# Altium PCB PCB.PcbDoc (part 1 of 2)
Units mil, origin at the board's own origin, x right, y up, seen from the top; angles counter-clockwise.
Board outline 3149.61 x 1968.5 mil, 4 copper layers (Top, GND, Power, Bottom), stack 59.37 mil thick; 127 components, 80 nets, 529 pads, 122 vias.
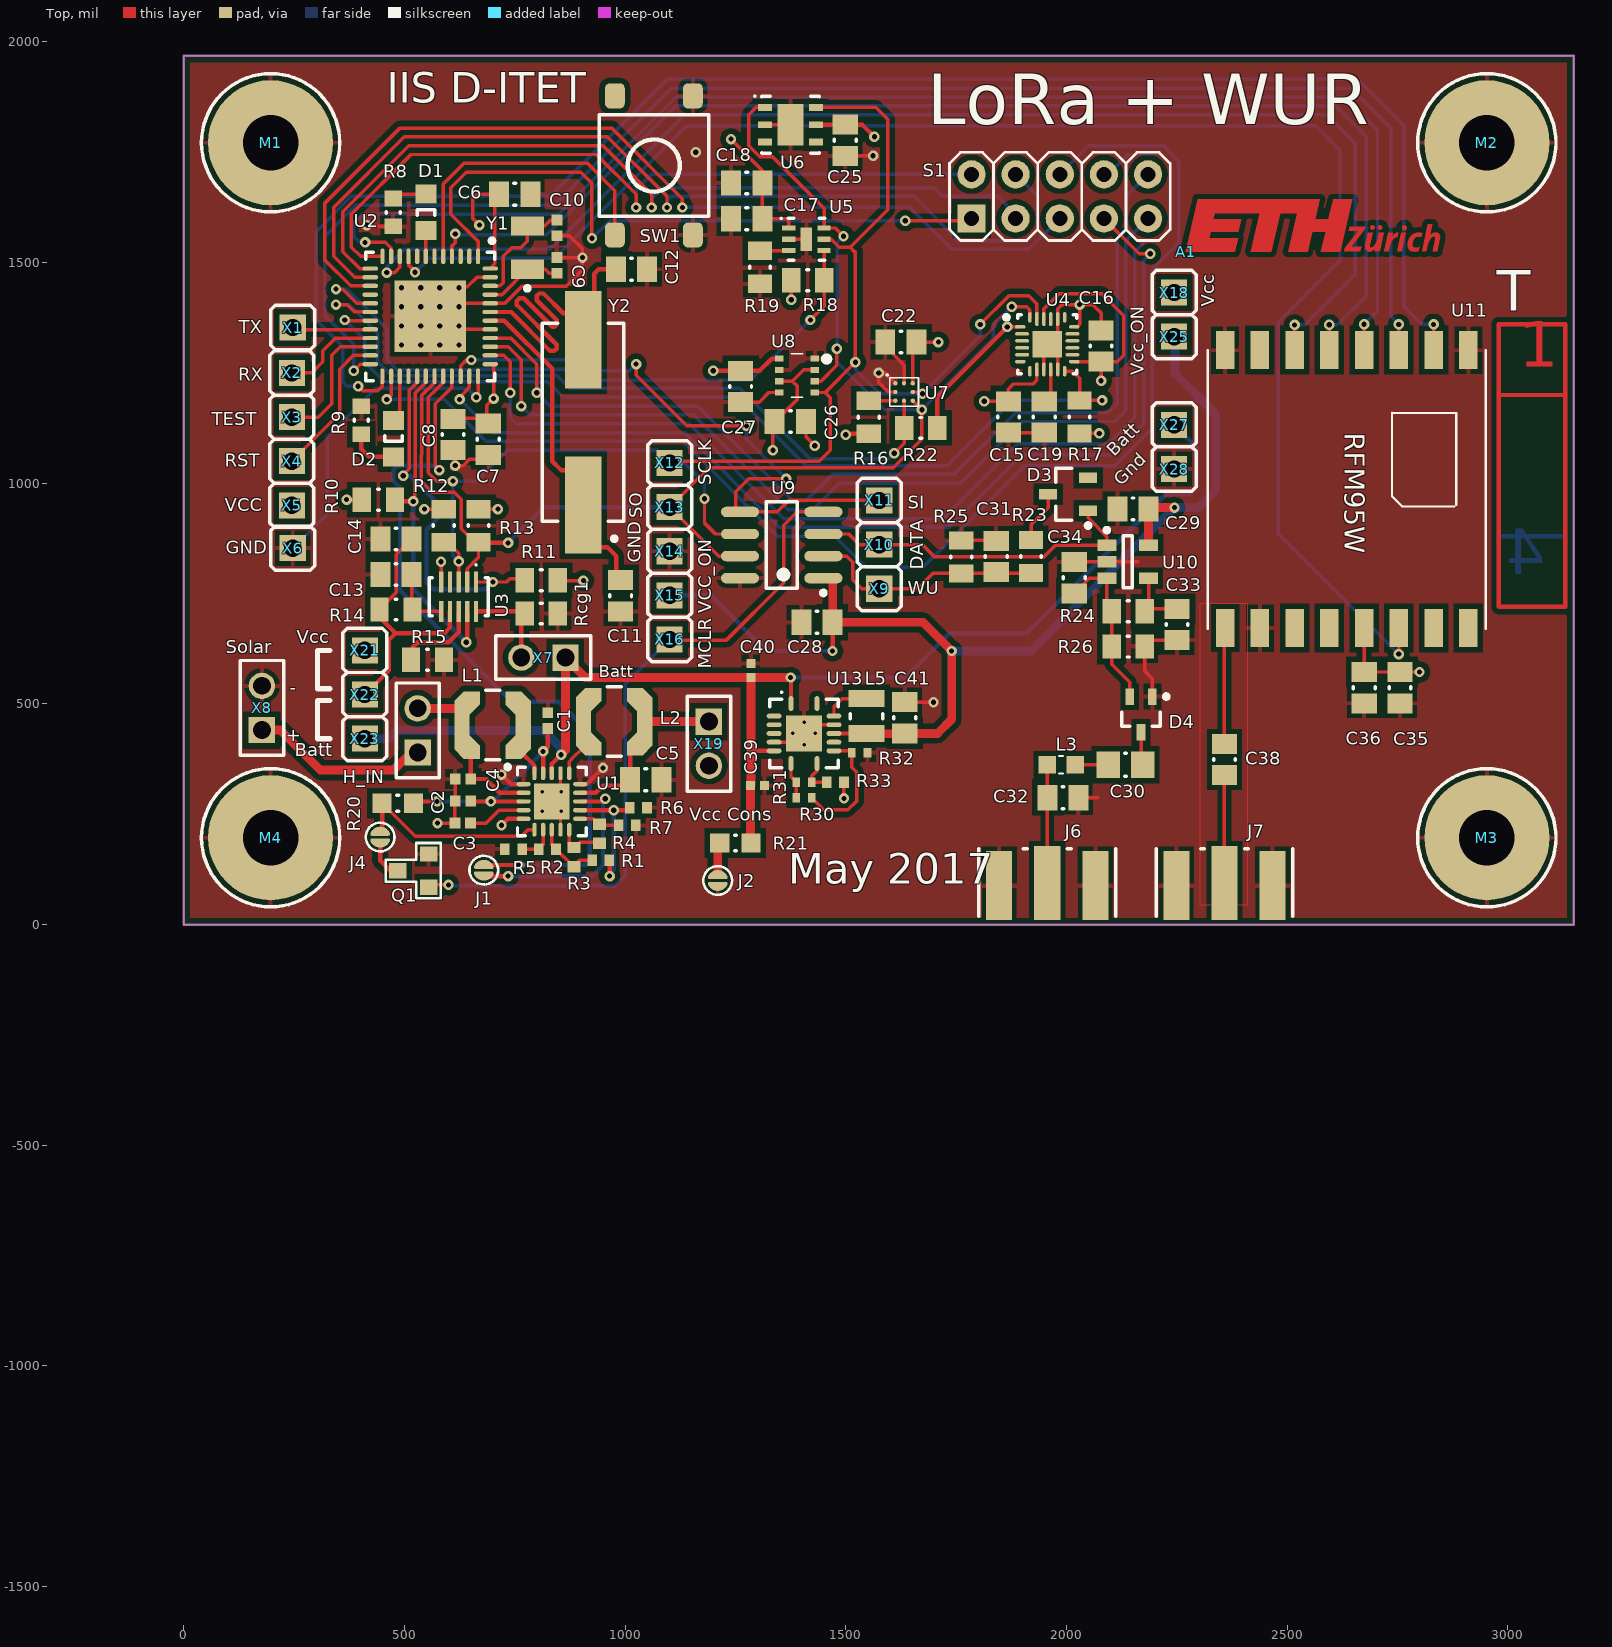
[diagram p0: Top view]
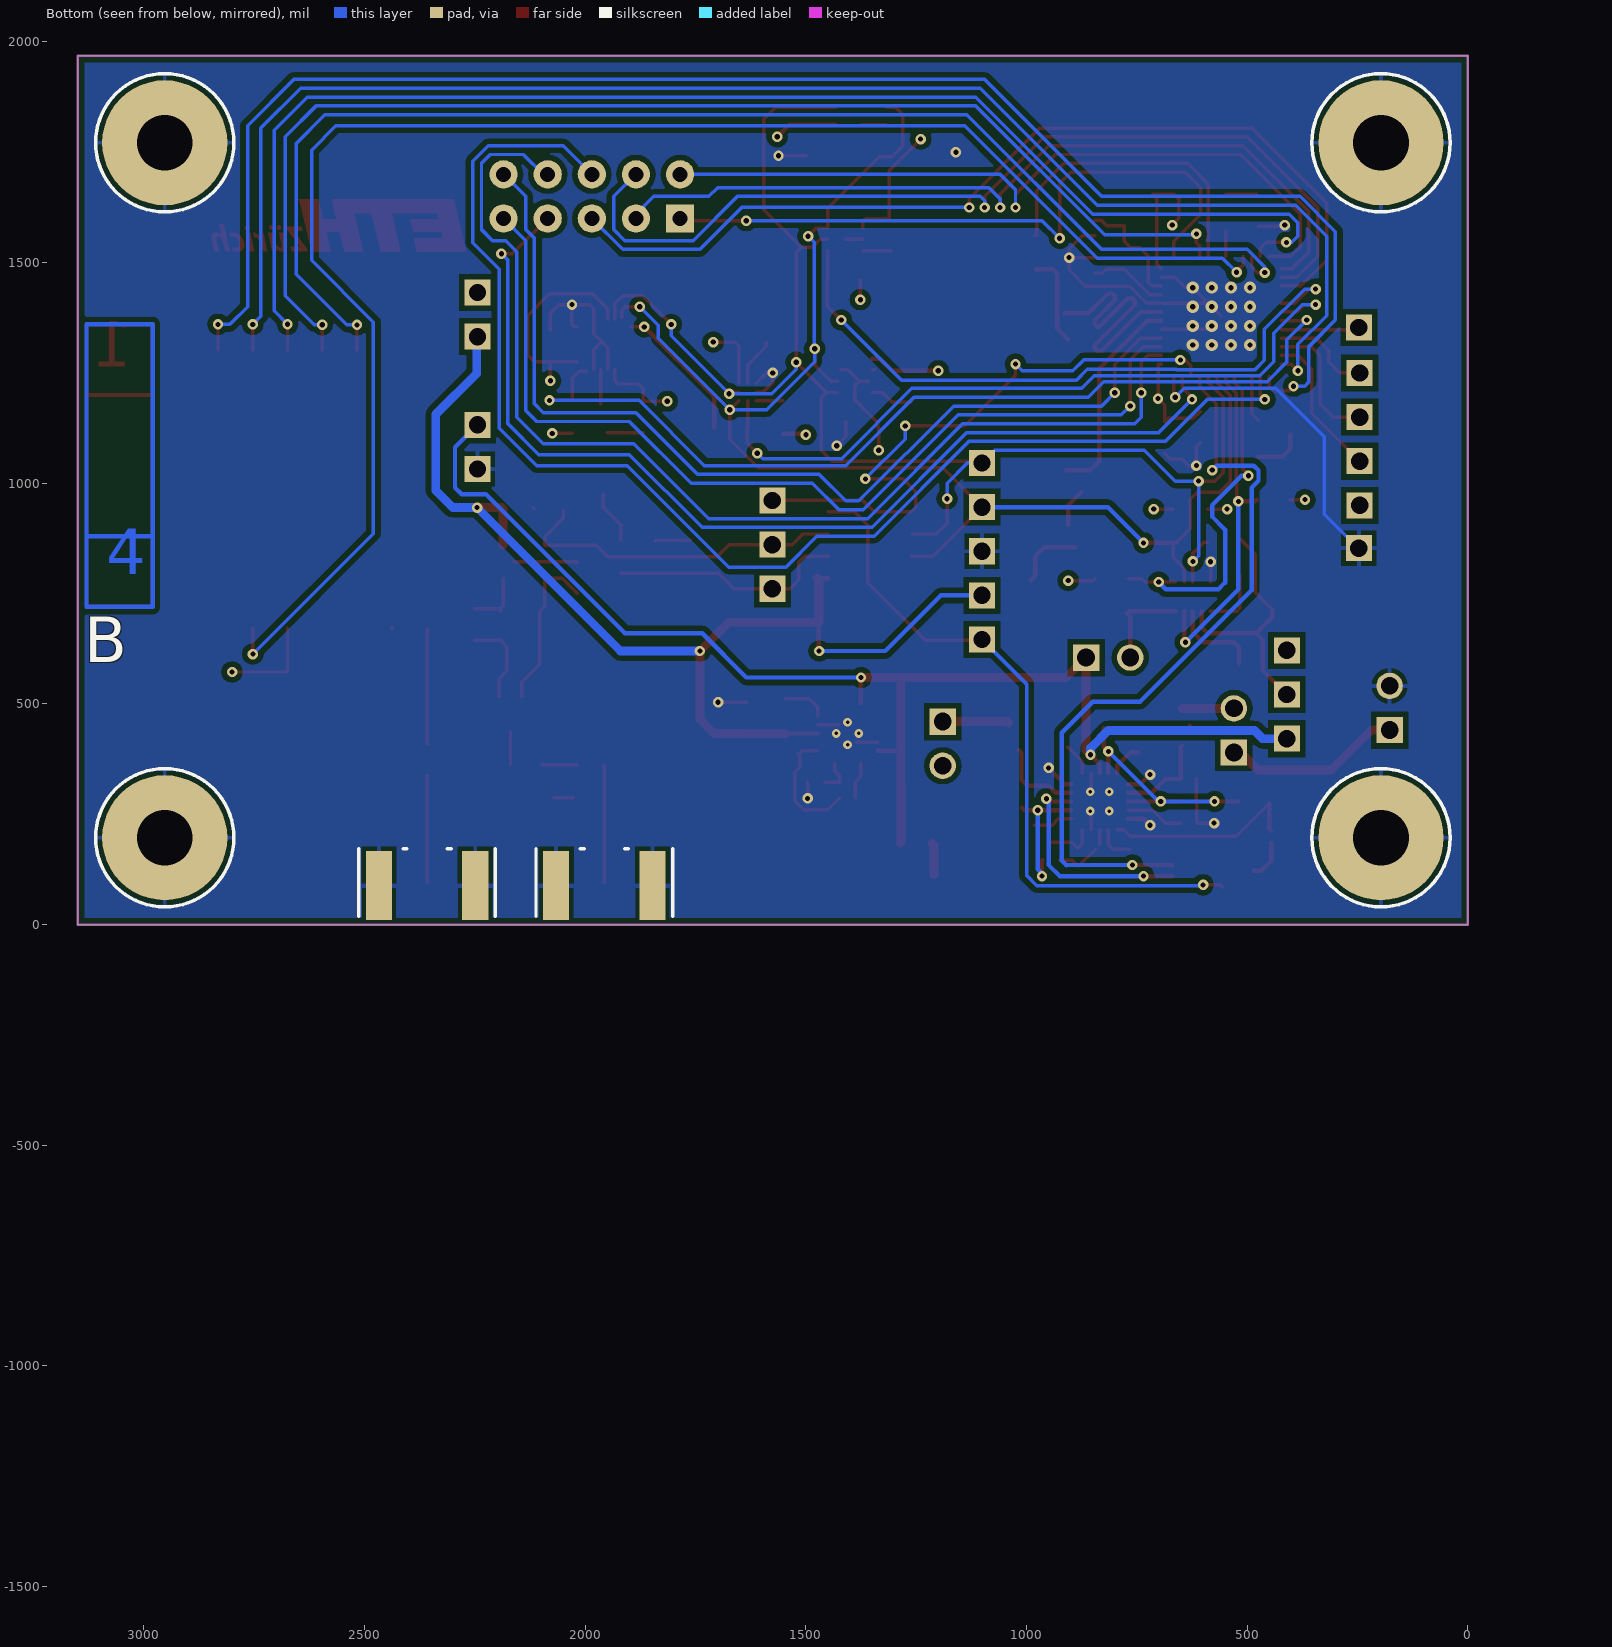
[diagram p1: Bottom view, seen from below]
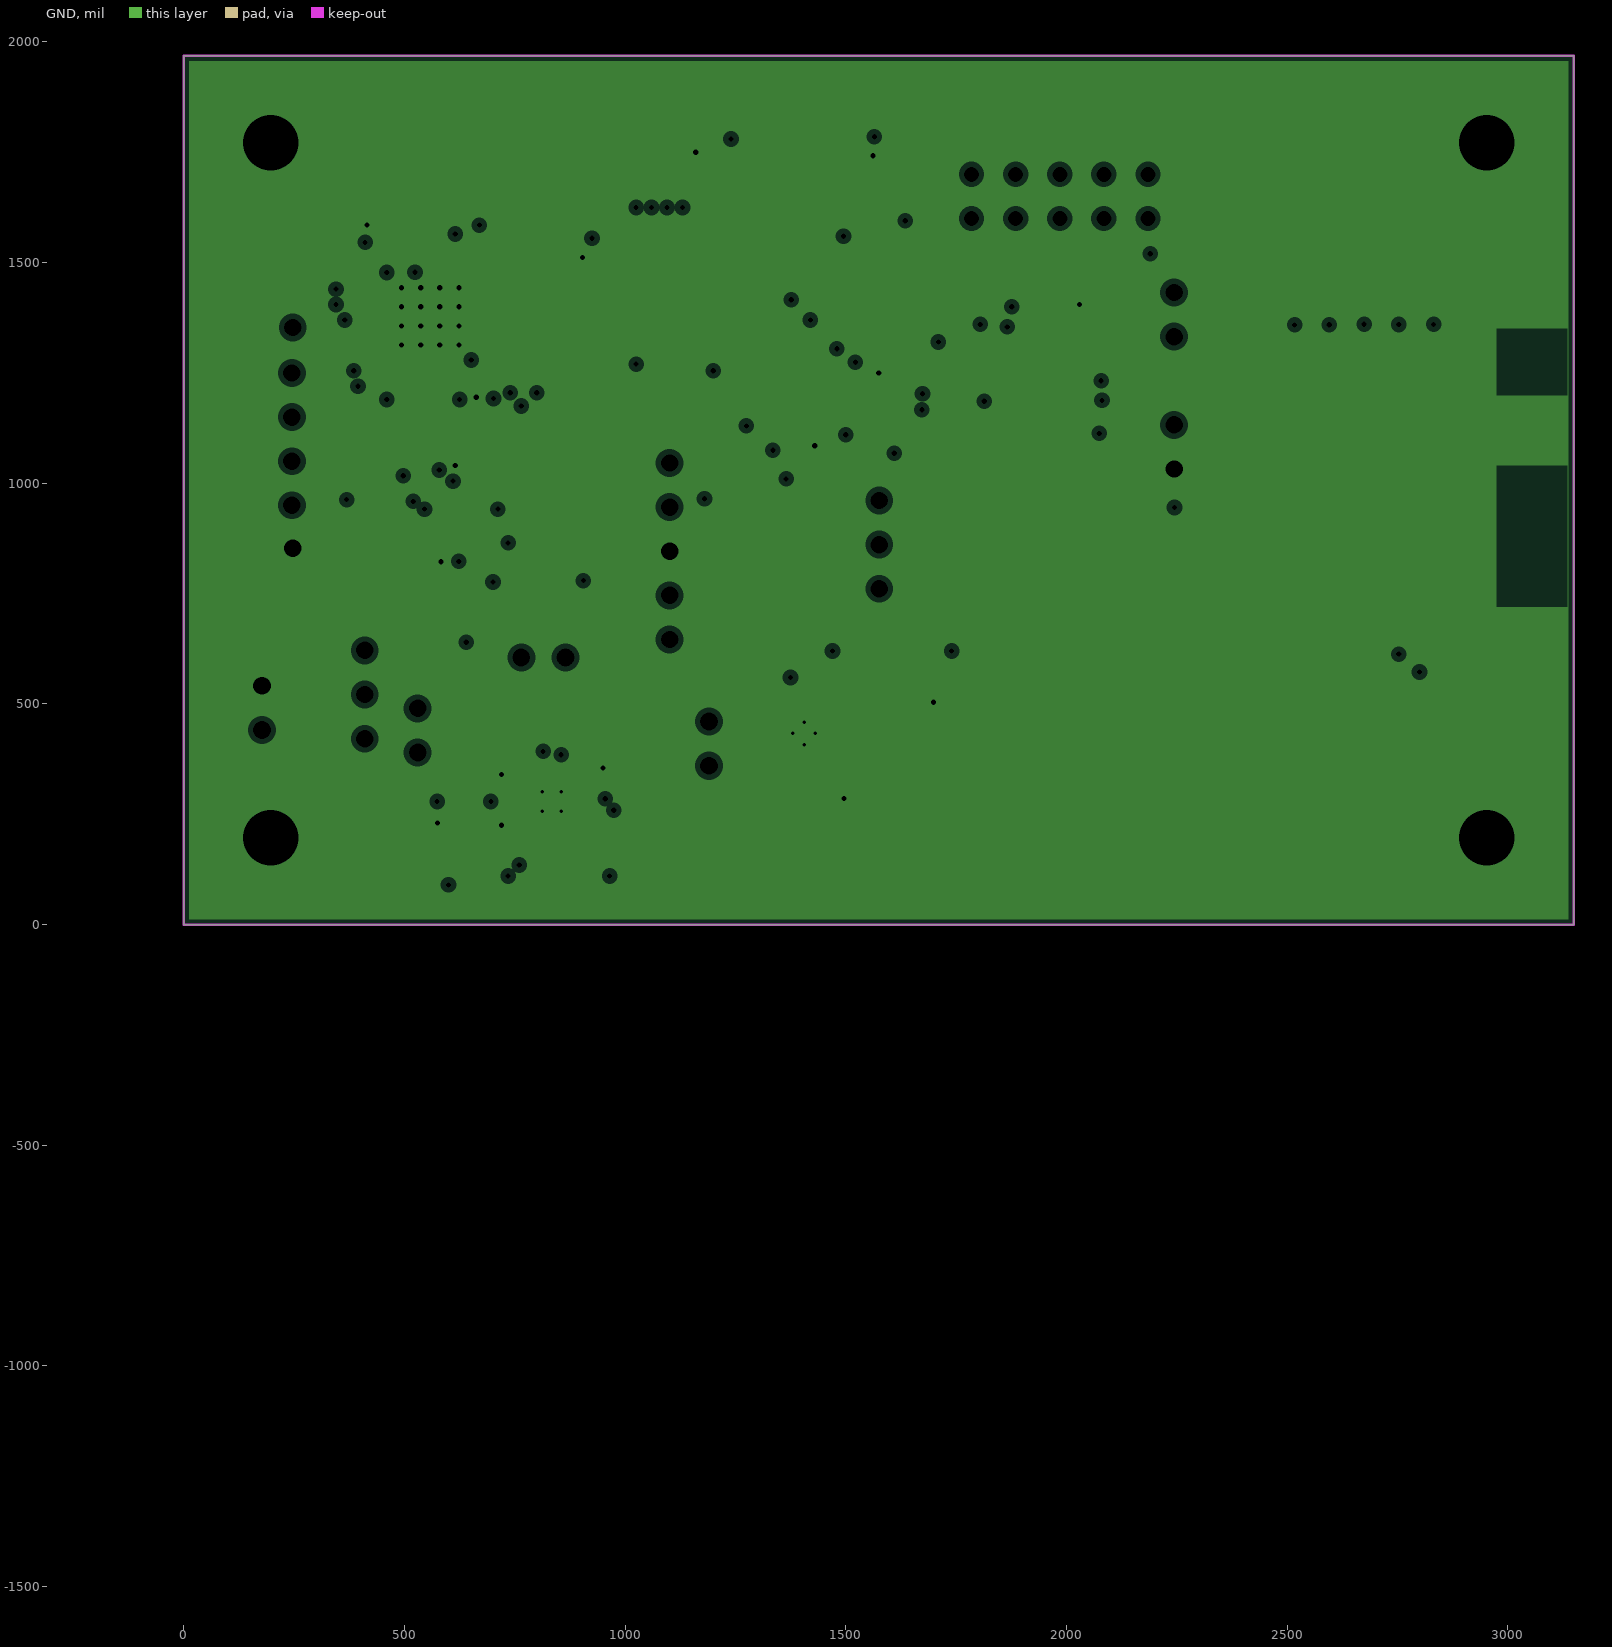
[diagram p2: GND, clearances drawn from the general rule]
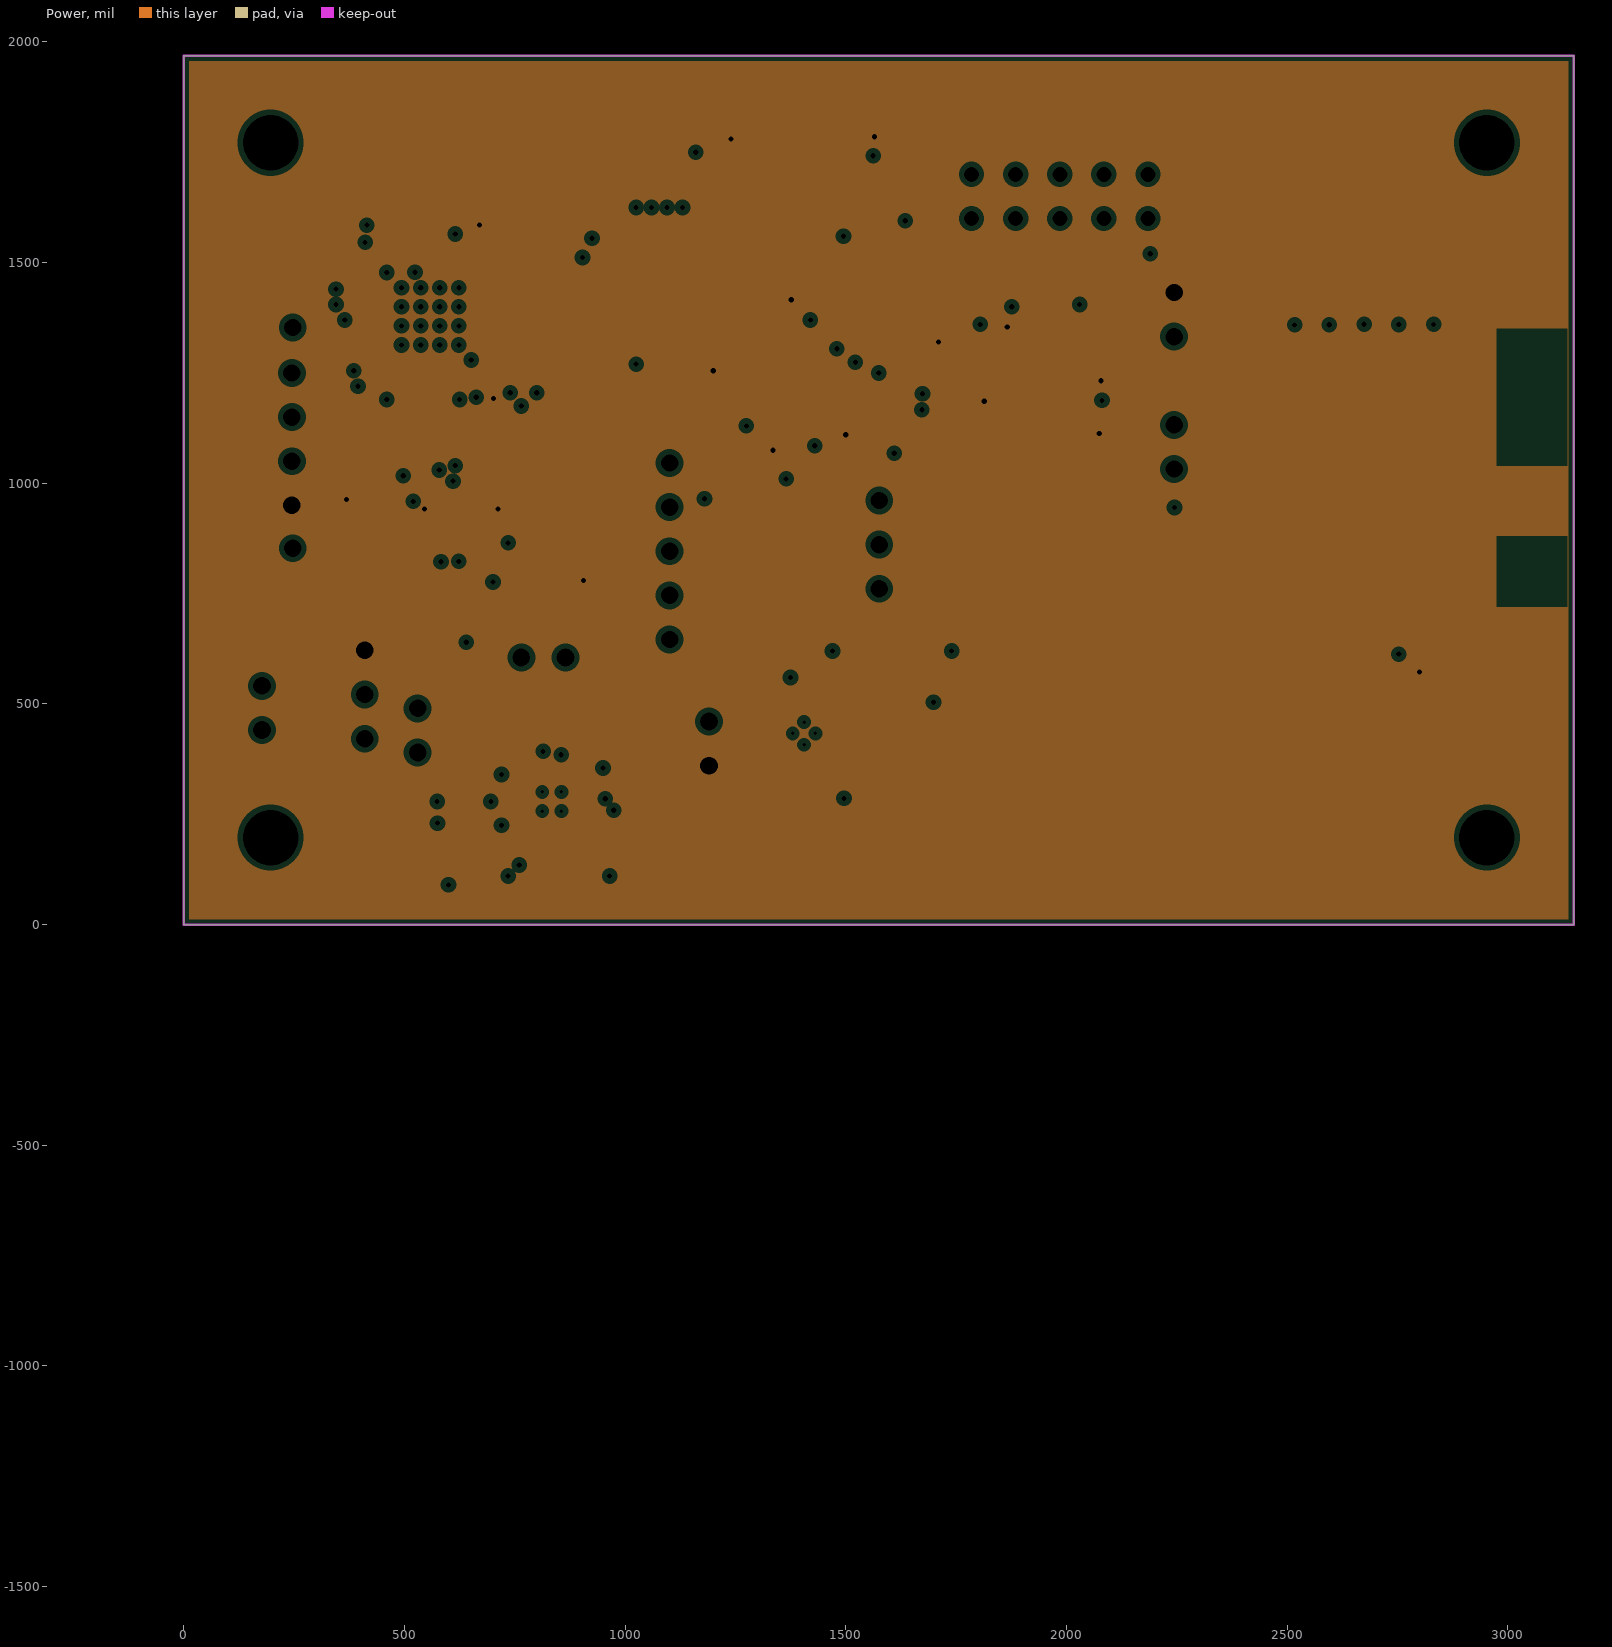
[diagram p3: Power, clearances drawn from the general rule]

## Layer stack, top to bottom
Top Solder: solder mask 0.9843, Solder Resist, Dk 3.5
Top: signal copper 1.4173
Dielectric1: prepreg 7.874, FR-4, Dk 4
GND: plane copper 0.7087, net GND
Dielectric4: core 39.3701, FR-4, Dk 4.2
Power: plane copper 0.7087, net VCC
Dielectric9: prepreg 7.874, FR-4, Dk 4.2
Bottom: signal copper 1.4173
Bottom Solder: solder mask 0.9843, Solder Resist, Dk 3.5

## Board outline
0,0 0,1968.5 3149.61,1968.5 3149.61,0

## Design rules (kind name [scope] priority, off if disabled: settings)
Clearance Clearance_Poly [InPolygon] p1: gap=12 ignorepadtopadclearanceinfootprint=FALSE except(0: Arc-Hole Track-Hole SMDPad-Hole THPad-Hole Via-Hole Fill-Hole Poly-Hole Region-Hole Text-Hole)
Clearance Clearance_RF [InNetClass('RF') vs InPolygon] p2: gap=11.81 ignorepadtopadclearanceinfootprint=FALSE except(0: Arc-Hole Track-Hole SMDPad-Hole THPad-Hole Via-Hole Fill-Hole Poly-Hole Region-Hole Text-Hole)
Clearance Clearance_SJ2 [InNet('NetJ2_1')] p3: gap=5 ignorepadtopadclearanceinfootprint=FALSE except(0: Arc-Hole Track-Hole SMDPad-Hole THPad-Hole Via-Hole Fill-Hole Poly-Hole Region-Hole Text-Hole)
Clearance Clearance_SJ4 [InNet('NetJ4_1')] p4: gap=5 ignorepadtopadclearanceinfootprint=FALSE except(0: Arc-Hole Track-Hole SMDPad-Hole THPad-Hole Via-Hole Fill-Hole Poly-Hole Region-Hole Text-Hole)
Clearance Clearance_SJ1 [InNet('NetJ1_1')] p5: gap=5 ignorepadtopadclearanceinfootprint=FALSE except(0: Arc-Hole Track-Hole SMDPad-Hole THPad-Hole Via-Hole Fill-Hole Poly-Hole Region-Hole Text-Hole)
Clearance [All] p6: gap=6 ignorepadtopadclearanceinfootprint=FALSE except(0: Arc-Hole Track-Hole SMDPad-Hole THPad-Hole Via-Hole Fill-Hole Poly-Hole Region-Hole Text-Hole)
ComponentClearance [All] p1 off: gap=10 collisioncheckmode=3 verticalgap=10 showdistances=FALSE
FabricationTestPointUsage TestPointUsage [All] p1: valid=0 allowmultiple=FALSE
FabricationTestpoint Testpoint [(IsPad And (OnTopLayer Or OnBottomLayer))] p1: side=3 testpointundercomponent=TRUE minsize=40 maxsize=100 preferedsize=60 minholesize=0 maxholesize=40 preferedholesize=32.01 testpointgrid=0.98 allowsidetop=TRUE allowsidebottom=TRUE usegrid=TRUE gridtolerance=0.01
Height [All] p1 off: minheight=0 maxheight=1000 prefheight=500
HoleSize [All] p1: absolutevalues=TRUE maxlimit=275.59 minlimit=7.87 maxpercent=80.000 minpercent=20.000
Length [InNetClass('Tektronic')] p1: maxlimit=3006 minlimit=2994
MinimumAnnularRing [All] p1 off: minimumring=5.91
MinimumSolderMaskSliver [All] p1: minsoldermaskwidth=3.9
PlaneClearance Spacer_Clearance [(InPadClass('Spacer') )] p1: clearance=78.74
PlaneClearance "Mounting holes" [(InPadClass('ExtendedClearance') )] p2: clearance=82.68
PlaneClearance [All] p3: clearance=11.81
PlaneConnect ViaInPlane [IsVia] p1: planeconnectstyle=Direct reliefexpansion=20 reliefentries=4 reliefconductorwidth=10 reliefairgap=10
PlaneConnect [All] p2: planeconnectstyle=Relief reliefexpansion=10 reliefentries=4 reliefconductorwidth=8 reliefairgap=8
PolygonConnect ViaInPolygon [IsVia] p1: connectstyle=Direct reliefconductorwidth=10 reliefentries=4 polygonreliefangle="90 Angle" airgapwidth=10
PolygonConnect [All] p2: connectstyle=Relief reliefconductorwidth=10 reliefentries=4 polygonreliefangle="90 Angle" airgapwidth=10
RoutingVias [All] p1: holewidth=11.81 width=23.62 viastyle="Through Hole" minholewidth=7.87 minwidth=17.72 maxholewidth=31.5 maxwidth=47.24
ShortCircuit ViaInPAD [InNet('No Net') vs InNet('No Net')] p1: allowed=TRUE
ShortCircuit RF_GNSs [InNet('D_GND') vs InNetClass('RF_GND')] p2: allowed=FALSE
ShortCircuit [All] p3: allowed=FALSE
SilkToSilkClearance [All] p1: silktosilkclearance=3.94
SilkToSolderMaskClearance [IsPad] p1: minsilkscreentomaskgap=3.94 clearancetoexposedcopper=TRUE
SolderMaskExpansion [All] p1: expansion=2.95
Width [All] p1: maxlimit=98.43 minlimit=5.91 preferedwidth=10 minimp=50.000000 maximp=50.000000 favimp=50.000000
19 further rules are at their usual default settings.

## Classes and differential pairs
pad class ExtendedClearance: O3216-A
pad class Vias: DPS8-A9
pad class Sense: DPS1-A6 DPS1-A12 DPS1-B5 DPS1-B7 DPS1-B11 DPS1-B13 DPS1-B17 DPS1-C2 DPS1-C6 DPS1-C12 DPS1-C16 DPS2-A6 DPS2-A12 DPS2-B3 DPS2-B5 DPS2-B11 DPS2-B13 DPS2-C2 DPS2-C6 DPS2-C12 DPS2-C16 DPS3-C12
pad class DirectConnect: 30501-1 30501-2 30501-3 30501-4 30501-5 30501-6 30501-7 30501-8 30501-9 30502-1 30502-2 30502-3 30502-4 30502-5 30502-6 30502-7 30502-8 30502-9 30503-1 30503-2 30503-3 30503-4 30503-5 30503-6 30503-7 30503-8 30503-9 30504-1 30504-2 30504-3 30504-4 30504-5 30504-6 30504-7 30504-8 30504-9
component class LoRa: C35 C36 C38 J7 JMS1 JMS2 JMS3 JMS4 JMS5 JMS6 JP5 JP6 JP7 NT_LED O1 T1 U11
component class Power: C1 C2 C3 C4 C5 H_IN J1 J4 L1 L2 Q1 R1 R2 R3 R4 R5 R6 R7 R20 U1 X19
component class MCU: C6 C7 C8 C9 C10 C11 C12 C13 C14 D1 D2 J2 R8 R9 R10 R11 R12 R13 R14 R15 R21 Rcg1 SW1 U2 U3 X21 X22 X23 Y1 Y2
component class Sensors: C15 C16 C17 C18 C19 C22 C25 C26 C27 R16 R17 R18 R19 R22 U4 U5 U6 U7 U8
component class WUR: C28 C29 C30 C31 C32 C33 C34 C39 C40 C41 D3 D4 J6 L3 L5 R23 R24 R25 R26 R30 R31 R32 R33 U9 U10 U13 X9 X10 X11 X12 X13 X14 X15 X16
net class RF: NetC30_1 NetC30_2 NetC32_2 NetC34_2 NetC38_1 NetC38_2 RF_DEM
component class Connectivity: A1 M1 M2 M3 M4 S1 X1 X2 X3 X4 X5 X6 X7 X8 X18 X25 X27 X28

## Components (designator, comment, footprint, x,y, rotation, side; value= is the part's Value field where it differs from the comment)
A1 "Logo ETH Zurich" eth-zurich_3mm 2270,1525 r0 top
C1 "CAP 4.7uF 6.3V 0402(1005)" CAPC0402(1005)60_N 825,462.28 r270 top value=4.7uF
C2 "CAP 100nF 25V 0402(1005)" CAPC0402(1005)60_N 632.72,280 r0 top value=100nF
C3 "CAP 10nF 25V 0402(1005)" CAPC0402(1005)60_N 632.28,230 r0 top value=10nF
C4 "CAP 4.7uF 6.3V 0402(1005)" CAPC0402(1005)60_N 632.72,330 r0 top value=4.7uF
C5 "CAP 22uF 6.3V 0805(2012)" CAPC0805(2012)145_N 1046.87,328.03 r180 top value=22uF
C6 "CAP 100nF 16V 0805(2012)" CAPC0805(2012)145_N 750,1655 r180 top value=100nF
C7 "CAP 100nF 16V 0805(2012)" CAPC0805(2012)145_N 690,1100 r90 top value=100nF
C8 "CAP 100nF 16V 0805(2012)" CAPC0805(2012)145_N 610,1110.43 r90 top value=100nF
C9 "CAP 15pF 25V 0402(1005)" CAPC0402(1005)60_N 845.81,1493.77 r90 top value=15pF
C10 "CAP 15pF 25V 0402(1005)" CAPC0402(1005)60_N 845.81,1578.77 r270 top value=15pF
C11 "CAP 27pF 10V 0805(2012)" CAPC0805(2012)100_N 990,745 r90 top value=27pF
C12 "CAP 27pF 10V 0805(2012)" CAPC0805(2012)100_N 1014.57,1485 r180 top value=27pF
C13 "CAP 220nF 16V 0805(2012)" CAPC0805(2012)145_N 480.87,793.03 r180 top value=220nF
C14 "CAP 1uF 16V 0805(2012)" CAPC0805(2012)145_N 480.87,874.03 r0 top value=1uF
C15 "CAP 10nF 16V 0805(2012)" CAPC0805(2012)100_N 1868.87,1150.43 r270 top value=10nF
C16 "CAP 100nF 16V 0805(2012)" CAPC0805(2012)145_N 2078.74,1311.02 r270 top value=100nF
C17 "CAP 1uF 16V 0805(2012)" CAPC0805(2012)145_N 1275.87,1599.43 r0 top value=1uF
C18 "CAP 100nF 16V 0805(2012)" CAPC0805(2012)145_N 1275.87,1680.43 r180 top value=100nF
C19 "CAP 100nF 16V 0805(2012)" CAPC0805(2012)145_N 1950.05,1150.43 r90 top value=100nF
C22 "CAP 100nF 16V 0805(2012)" CAPC0805(2012)145_N 1625,1320 r180 top value=100nF
C25 "CAP 100nF 16V 0805(2012)" CAPC0805(2012)145_N 1498.87,1777.43 r270 top value=100nF
C26 "CAP 100nF 16V 0805(2012)" CAPC0805(2012)145_N 1374.57,1140 r0 top value=100nF
C27 "CAP 100nF 16V 0805(2012)" CAPC0805(2012)145_N 1261.87,1219.43 r270 top value=100nF
C28 "CAP 100nF 16V 0805(2012)" CAPC0805(2012)145_N 1435,685 r0 top value=100nF
C29 "CAP 100nF 16V 0805(2012)" CAPC0805(2012)145_N 2150.91,942.06 r0 top value=100nF
C30 "CAP 100pF 16V 0805(2012)" CAPC0805(2012)100_M 2133.86,362.2 r180 top value=100pF
C31 "CAP 4.7nF 16V 0805(2012)" CAPC0805(2012)145_N 1840.91,834.06 r270 top value=4.7nF
C32 "CAP 3.3pF 10V 0805(2012)" CAPC0805(2012)75_N 1992.13,287.4 r180 top value=3.3pF
C33 "CAP 4.7nF 16V 0805(2012)" CAPC0805(2012)145_N 2250.91,680.06 r90 top value=4.7nF
C34 "CAP 12pF 25V 0805(2012)" CAPC0805(2012)100_N 2017.91,786.06 r270 top value=12pF
C35 "CAP 100nF 16V 0805(2012)" CAPC0805(2012)145_N 2755.8,536.93 r270 top value=100nF
C36 "CAP 100nF 16V 0805(2012)" CAPC0805(2012)145_N 2674.8,536.93 r270 top value=100nF
C38 "CAP 100nF 16V 0805(2012)" CAPC0805(2012)145_N 2358.27,374.02 r90 top value=100nF
C39 "CAP 4.7uF 6.3V 0402(1005)" CAPC0402(1005)60_L 1300,315 r180 top value=4.7uF
C40 "CAP 100nF 25V 0402(1005)" CAPC0402(1005)60_L 1285,575.75 r270 top value=100nF
C41 "CAP 22uF 6.3V 0805(2012)" CAPC0805(2012)145_N 1633.86,468.51 r270 top value=22uF
D1 "150080YS75000" 0805_A 548.68,1613.77 r270 top
D2 "150080YS75000" 0805_A 475,1101.34 r90 top
D3 "BAT17" INF-SOT23_N 2003.91,975.06 r180 top
D4 "HSMS-285C-BLKG" INF-SOT323_N 2169.29,476.38 r270 top
H_IN "H_IN" "Pin Header, 1x2" 530,390 r90 top (schematic designator X17)
J1 "Solder Jumper" "Small Solder Jumper" 680,123.29 r270 top value=1
J2 "Solder Jumper" "Small Solder Jumper" 1210,100 r270 top value=1
J4 "Solder Jumper" "Small Solder Jumper" 445,198.29 r270 top value=1
J6 "132322" 132322 1956.69,94.49 r270 top
J7 "132322" 132322 2358.27,94.49 r270 top
L1 "LPS4018-223MR" COILCRAFT-IND-LPS4018 699.87,452.03 r0 top
L2 "LPS4018-103MR" COILCRAFT-IND-LPS4018 975.2,459.76 r0 top
L3 "LQW18AN30NJ00D" INDC0603(1608)_N 1988.19,362.2 r0 top
L5 "1239AS-H-100M=P2" INDC2520X10L 1547.24,472.44 r270 top
M1 "Mounting Hole" "Hole M3" 196.85,1771.65 r0 top locked
M2 "Mounting Hole" "Hole M3" 2952.76,1771.65 r0 top locked
M3 "Mounting Hole" "Hole M3" 2952.76,196.85 r0 top locked
M4 "Mounting Hole" "Hole M3" 196.85,196.85 r0 top locked
Q1 "FDN339AN" FDN339AN 555,85 r90 top
R1 "7M87" RESC0402(1005)_N 944.87,146.03 r180 top value="7870000.00 Ohm"
R2 "7M32" RESC0402(1005)_N 823.87,171.03 r0 top value=7.32Meg
R3 "698K" RESC0402(1005)_M 883.87,153.03 r270 top value="698000.00 Ohm"
R4 "6M81" RESC0402(1005)_M 941.87,205.86 r270 top value="6810000.00 Ohm"
R5 "5M49" RESC0402(1005)_N 746.87,171.03 r0 top value=5.49Meg
R6 "5M23" RESC0402(1005)_N 1030,265 r180 top value="5230000.00 Ohm"
R7 "5M49" RESC0402(1005)_N 1005,225 r180 top value="5490000.00 Ohm"
R8 "470R" RESC0603(1608)_N 474.53,1613.77 r270 top value="470.00 Ohm"
R9 "470R" RESC0603(1608)_N 402.49,1142.77 r90 top value="470.00 Ohm"
R10 "1K 1% 0805(2012)" RESC0805(2012)_N 441,963 r0 top value=1K
R11 "10K 1% 0805(2012)" RESC0805(2012)_N 810,780 r180 top value=10K
R12 "3K3 1% 0805(2012)" RESC0805(2012)_N 588.87,904.03 r90 top value=3.3k
R13 "3K3 1% 0805(2012)" RESC0805(2012)_N 667.87,904.03 r90 top value=3.3k
R14 "1K 1% 0805(2012)" RESC0805(2012)_N 480.87,714.03 r180 top value=1K
R15 "1K 1% 0805(2012)" RESC0805(2012)_N 552.4,600 r180 top value=1K
R16 "10K 1% 0805(2012)" RESC0805(2012)_N 1551.87,1149.43 r90 top value=10K
R17 "10K 1% 0805(2012)" RESC0805(2012)_N 2029.87,1150.43 r270 top value=10K
R18 "10K 1% 0805(2012)" RESC0805(2012)_N 1413.87,1460.43 r180 top value=10K
R19 "499K 1% 0805(2012)" RESC0805(2012)_N 1305.87,1489.43 r90 top value=499K
R20 "1M" RESC0603(1608)_M 485,275 r180 top value="1020000.00 Ohm"
R21 "1M" RESC0603(1608)_M 1250,185 r180 top value="1020000.00 Ohm"
R22 "10K 1% 0805(2012)" RESC0805(2012)_N 1669.87,1125.43 r180 top value=10K
R23 "84K5 1% 0805(2012)" RESC0805(2012)_N 1919.91,834.06 r270 top value=84.5K
R24 "1M5 1% 0805(2012)" RESC0805(2012)_N 2140,710 r180 top value=1.5Meg
R25 "1M 1% 0805(2012)" RESC0805(2012)_N 1761.91,833.06 r270 top value=1Meg
R26 "3M 1% 0805(2012)" RESC0805(2012)_N 2140,630 r180 top value=3Meg
R30 "7M68 1% 0402(1005)" RESC0402(1005)_L 1405.51,287.4 r180 top value=7.68Meg
R31 "7M87 1% 0402(1005)" RESC0402(1005)_L 1405.51,322.84 r180 top value=7.87Meg
R32 "5M23 1% 0402(1005)" RESC0402(1005)_L 1531.5,389.77 r180 top value=5.23Meg
R33 "5M1 1% 0402(1005)" RESC0402(1005)_N 1476.38,322.84 r180 top value=5.1Meg
Rcg1 "UCR10EVHFSR050" RESC0805(2012)_N 810,705 r180 top value=0.05R
S1 "SIP-5x2" SIP-5x2 1785,1600 r0 top
SW1 "ADTSM62RVTR" SW_DTSM-62N 1065,1720 r90 top
U1 "BQ25570RGRT" QFN50P350X350X100_HS-21L 834.05,279.03 r0 top
U2 "MSP430FR5969IRGZT" QFN-48-7x7-4.1x4.1_N 558.53,1378.34 r270 top
U3 "STC3115IQT" SON50P200X60-10N 622.87,743.03 r270 top
U4 "MPU-9250" MPU-9250 1956.69,1314.96 r0 top
U5 "ISL29023IROZ-T7" SON65P210X75_HS-7N 1410.85,1552.87 r0 top
U6 "SHT21" SON100P300X110_HS-7N 1374.87,1812.43 r0 top
U7 "TMP006BIYZFR" YZF0008AHAH 1632.21,1206.87 r0 top
U8 "BME280" BME280 1389.76,1244.09 r0 top
U9 "PIC12LF1552-I/SN" M08A_N 1354.91,860.06 r180 top
U10 "TLV3701CDBVT" Z5+1_N 2138.91,822.06 r0 top
U11 "RFM95W-868S2" RFM95W 2635.24,986.59 r270 top
U13 "TPS62736RGYR" RGY14-2050X2050TP 1405.51,433.07 r0 top
X1 "TX" TSW-150-07-G-S 247,1353 r0 top
X2 "RX" TSW-150-07-G-S 245,1250 r0 top
X3 "TEST" TSW-150-07-G-S 245,1150 r0 top
X4 "RST" TSW-150-07-G-S 245,1050 r0 top
X5 "VCC" TSW-150-07-G-S 245,950 r0 top
X6 "GND" TSW-150-07-G-S 247,853 r0 top
X7 "Batt" "Pin Header, 1x2" 865,605 r180 top
X8 "Solar" "Pin Header, 1x2" 177.17,440.94 r90 top
X9 "WU" TSW-150-07-G-S 1575.92,761.05 r90 top
X10 "DATA" TSW-150-07-G-S 1575.92,861.05 r90 top
X11 "SI" TSW-150-07-G-S 1575.92,961.05 r90 top
X12 "SCLK" TSW-150-07-G-S 1100.92,1046.06 r270 top
X13 "SO" TSW-150-07-G-S 1100.92,946.06 r270 top
X14 "GND" TSW-150-07-G-S 1100.92,846.06 r270 top
X15 "VCC_ON" TSW-150-07-G-S 1100.92,746.06 r270 top
X16 "MCLR" TSW-150-07-G-S 1100.92,646.06 r270 top
X18 "Vcc" TSW-150-07-G-S 2244.09,1432.28 r0 top
X19 "Vcc Cons" "Pin Header, 1x2" 1190,460 r270 top
X21 "Vcc" TSW-150-07-G-S 410.24,621.26 r0 top
X22 "" TSW-150-07-G-S 410.24,521.26 r0 top
X23 "Batt" TSW-150-07-G-S 410.24,421.26 r0 top
X25 "Vcc_ON" TSW-150-07-G-S 2244.09,1332.28 r0 top
X27 "Batt" TSW-150-07-G-S 2244.09,1132.28 r0 top
X28 "Gnd" TSW-150-07-G-S 2244.09,1032.28 r0 top
Y1 "ABS07-32.768KHz-T" ABRA-ABS07-2_V 778.53,1534.17 r90 top
Y2 "ABLS2-4.096MHZ-D4Y-T" ABRA-ABLS2-2_V 905,1137.99 r90 top

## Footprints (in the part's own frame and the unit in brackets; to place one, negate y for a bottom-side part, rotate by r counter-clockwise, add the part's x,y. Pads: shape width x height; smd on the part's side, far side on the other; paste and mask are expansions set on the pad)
0805_A [mm] "Chip LED, 2-Leads, Body 2.0x1.3mm, IPC Medium Density"
  rect 1.1x1.2 smd: 1(-1.05,0) 2(1.05,0)
  silkscreen extent -0.15,-0.5 0.15,0.5, body extent -1,-0.62 1,0.63, height 0.68
132322 [mm] "Connector, SMA Female Edge Mount for 0.062\" Thick Board, 5-Lead, Body Dia. 6.4mm"
  rect 4.25x1.5 smd: 1(0,0)
  rect 3.95x1.5 smd: 2(0.15,-2.77) 5(0.15,2.77)
  rect 3.95x1.5 smd far side: 3(0.15,-2.77) 4(0.15,2.77)
  silkscreen extent -1.97,-3.93 1.93,3.93, body extent -1.38,-3.17 11.95,3.18, height 3.56
ABRA-ABLS2-2_V [mm] "SMD, 2-Leads, Body 11.4x4.7mm, Height 3.3mm"
  rect 5.6x2.1 smd: 1(-4.75,0) 2(4.75,0)
  silkscreen extent -6.82,-2.35 5.7,2.35, body extent -5.7,-2.35 5.7,2.35, height 3.3
ABRA-ABS07-2_V [mm] "Hand Drawn, 2-Leads, Body 3.2x1.5mm, Pitch 2.5mm"
  rect 1.1x1.9 smd: 1(-1.25,0) 2(1.25,0)
  silkscreen extent -2.47,-0.13 -2.23,0.12, body extent -1.6,-0.75 1.6,0.75, height 0.9
BME280 [mm] "LGA, 8-Leads, Body 2x2.50mmx0.95mm, Pitch 0.65mm"
  rect 0.5x0.35 smd: 1(1.025,0.975) 2(1.025,0.325) 3(1.025,-0.325) 4(1.025,-0.975) 5(-1.025,-0.975) 6(-1.025,-0.325) 7(-1.025,0.325) 8(-1.025,0.975)
  silkscreen extent -0.33,-1.25 1.83,1.25, body extent -1.25,-1.25 1.25,1.25, height 0.94
CAPC0402(1005)60_L [mm] "Chip Capacitor, Body 1.0x0.5mm, Height 0.6mm, IPC High Density"
  rect 0.52x0.52 smd: 1(-0.4,0) 2(0.4,0)
  body extent -0.55,-0.3 0.55,0.3, height 0.6
CAPC0402(1005)60_N [mm] "Chip Capacitor, Body 1.0x0.5mm, Height 0.6mm, IPC Medium Density"
  rect 0.62x0.62 smd: 1(-0.45,0) 2(0.45,0)
  body extent -0.55,-0.3 0.55,0.3, height 0.6
CAPC0805(2012)75_N [mm] "Chip Capacitor, Body 2.0x1.2mm, Height 0.75mm, IPC Medium Density"
  rect 1.15x1.45 smd: 1(-0.9,0) 2(0.9,0)
  silkscreen extent -0.05,-0.62 0.05,0.63, body extent -1.1,-0.72 1.1,0.73, height 0.75
CAPC0805(2012)100_M [mm] "Chip Capacitor, Body 2.0x1.2mm, Height 1.0mm, IPC Low Density"
  rect 1.35x1.55 smd: 1(-1,0) 2(1,0)
  silkscreen extent -0.05,-0.67 0.05,0.67, body extent -1.1,-0.72 1.1,0.72, height 1
CAPC0805(2012)100_N [mm] "Chip Capacitor, Body 2.0x1.2mm, Height 1.0mm, IPC Medium Density"
  rect 1.15x1.45 smd: 1(-0.9,0) 2(0.9,0)
  silkscreen extent -0.05,-0.62 0.05,0.63, body extent -1.1,-0.72 1.1,0.73, height 1
CAPC0805(2012)145_N [mm] "Chip Capacitor, Body 2.0x1.2mm, Height 1.45mm, IPC Medium Density"
  rect 1.15x1.45 smd: 1(-0.9,0) 2(0.9,0)
  silkscreen extent -0.05,-0.62 0.05,0.63, body extent -1.1,-0.72 1.1,0.73, height 1.45
COILCRAFT-IND-LPS4018 [mm] "Shielded Power Inductor, Body 4.0x4.0x1.8mm"
  rrect1% 0.87x2.79 smd: 1(-1.765,0) 2(1.765,0)
  rrect1% 0.785x0.785 smd rot 45: 1(-1.646,-1.391) 2(1.646,1.391)
  rrect1% 0.785x0.785 smd rot 135: 1(-1.646,1.391) 2(1.646,-1.391)
  rrect1% 0.85x0.85 smd rot 45: 1(-1.339,-1.172) 2(1.339,1.172)
  rrect1% 0.85x0.85 smd rot 135: 1(-1.339,1.172) 2(1.339,-1.172)
  rrect1% 0.91x0.775 smd: 1(-1.195,-1.558) 1(-1.195,1.558) 2(1.195,-1.558) 2(1.195,1.558)
  silkscreen extent -0.4,-2 0.4,2, body extent -2.05,-2.05 2.05,2.05, height 1.8
eth-zurich_3mm [mil] "Logo ETH Zurich"
  Top circle w10.63: c423.78,54.69 r0.04
  Top circle w10.63: c440.67,54.69 r0.04
  Top circle w11.81: c496,54.04 r0.04
  Top region: 350.2,0 350.2,0 377.95,118.11 334.37,118.11 323.92,73.64 293.68,73.64 304.07,118.11 27.76,118.11 0,0 46.12,0 111.73,0 118.94,30.71 53.39,30.71 56.75,45.12 119.47,45.12 126.14,73.46 63.37,73.46 66.67,87.4 168.25,87.4 147.64,0 193.82,0 214.37,87.4 253.29,87.4 232.8,0 276.38,0 287.01,45.3 317.24,45.3 306.61,0
  Top region: 407.83,56.69 407.83,56.69 372.11,56.69 369.92,46.89 391.54,46.89 361.12,7.26 359.76,0.94 395.43,0.94 397.62,10.75 375.94,10.75 406.48,50.55
  Top region: 439.61,0.94 439.61,0.94 448.76,42.17 437.83,42.17 434.29,26.04 432.28,21.26 429.92,17.01 427.56,13.23 425.2,10.75 423.31,9.45 421.42,8.5 420,8.5 418.58,8.98 417.64,9.92 417.4,11.34 417.4,13.23 417.64,14.88 423.72,42.17 413.21,42.17 408.66,21.26 406.95,13.46 406.77,9.92 407.24,6.61 408.19,3.78 410.08,1.89 412.44,0.47 414.33,0 418.11,0 421.89,0.94 425.2,2.83 427.68,5.31 430.39,8.5 428.74,0.94
  Top region: 466.83,30.71 466.83,30.71 469.37,42.17 459.69,42.17 450.53,0.94 460.22,0.94 461.69,7.62 463.94,14.88 466.54,21.26 468.66,25.28 471.61,29.17 473.62,31.18 475.28,32.36 476.93,33.07 478.11,33.07 479.7,32.66 481.89,42.52 480.47,42.76 479.06,42.76 477.64,42.52 475.51,41.57 474.09,40.63 472.2,38.98 470.55,37.32 468.66,34.49
  Top region: 489.69,0.94 489.69,0.94 498.84,42.17 489.15,42.17 480,0.94
  Top region: 535.98,41.4 535.98,41.4 533.86,42.17 531.5,42.52 527.72,42.52 523.46,42.17 518.98,41.1 515.2,39.21 512.13,36.85 510.24,34.96 508.35,32.6 506.69,29.76 505.51,26.93 504.33,23.62 503.62,20.55 503.15,17.48 503.15,13.46 503.62,9.92 504.33,7.56 505.51,5.2 506.93,3.31 508.82,1.89 510.94,0.94 513.07,0.47 517.8,0 520.16,0 524.41,0.47 527.07,1.12 528.19,1.42 529.19,10.69 527.01,9.92 523.94,9.21 521.57,8.98 519.92,8.98 518.03,9.45 516.38,10.39 515.43,11.34 514.72,12.76 514.25,14.41 514.02,16.06 514.02,18.19 514.49,21.26 515.43,24.33 516.61,26.93 518.03,29.06 520.16,31.65 522.05,32.83 523.94,33.54 525.83,33.78 528.66,33.78 531.26,33.54 532.44,33.31 534.09,32.83
  Top region: 555.83,37.8 555.83,37.8 553.11,34.61 559.07,61.48 549.39,61.48 535.98,0.94 545.67,0.94 549.21,17.07 551.22,21.85 553.58,26.1 555.94,29.88 558.31,32.36 560.2,33.66 562.09,34.61 563.5,34.61 564.92,34.13 565.87,33.19 566.1,31.77 566.1,29.88 565.87,28.23 559.78,0.94 570.3,0.94 574.84,21.85 576.56,29.65 576.73,33.19 576.26,36.5 575.32,39.33 573.43,41.22 571.06,42.64 569.17,43.11 565.39,43.11 561.61,42.17 558.31,40.28
FDN339AN [mil] "N-Channel Power MOSFET"
  rect 35x40 smd: 1(0,0) 2(75,0) 3(37,70)
  silkscreen extent -25,-27 100,97, body extent -25,10 100,65, height 44
"Hole M3" [mm] "Plated Thru-Hole, 3.2mm hole, 7.2mm pad"
  round 7.2 hole 3.2: 1(0,0)
  silkscreen extent -3.98,-3.98 3.98,3.98
INDC0603(1608)_N [mm] "Chip Inductor, 0603(1608), IPC Medium Density"
  rect 1x1 smd: 1(-0.8,0) 2(0.8,0)
  silkscreen extent -0.13,-0.5 0.13,0.5, body extent -0.9,-0.5 0.9,0.5, height 0.8
INDC2520X10L [mm] "Chip Inductor, 2-Leads, Body 2.50x2.00mm, IPC High Density"
  rect 0.98x2.08 smd: 1(-1.01,0) 2(1.01,0)
  silkscreen extent -0.15,-0.94 0.15,0.94, body extent -1.33,-1.07 1.32,1.08, height 1
INF-SOT23_N [mm] "SOT23, 3-Leads, Body 2.9x1.3 mm, Pitch 0.95 mm, IPC Medium Density"
  rect 1.05x0.6 smd: 1(-1.15,0.95) 2(-1.15,-0.95) 3(1.15,0)
  silkscreen extent -1.28,-1.5 0.7,1.92, body extent -0.7,-1.5 0.7,1.5, height 1.1
INF-SOT323_N [mm] "SOT23, 3-Leads, Body 2x1.25 mm, Pitch 0.65 mm, IPC Medium Density"
  rect 0.95x0.5 smd: 1(-1.025,0.65) 2(-1.025,-0.65) 3(1.025,0)
  silkscreen extent -1.15,-1.1 0.67,1.58, body extent -0.67,-1.1 0.67,1.1, height 1
M08A_N [mm] "SOIC, 8-Leads, Body 4.9x3.9mm, Pitch 1.27mm, IPC Medium Density"
  oval 2.2x0.6 smd: 1(-2.4,1.905) 2(-2.4,0.635) 3(-2.4,-0.635) 4(-2.4,-1.905) 5(2.4,-1.905) 6(2.4,-0.635) 7(2.4,0.635) 8(2.4,1.905)
  silkscreen extent -2.53,-2.5 0.9,2.88, body extent -2,-2.5 2,2.5, height 1.75
MPU-9250 [mm] "MPU-9250 QFN 24-Leads"
  oval 0.6x0.2 smd mask+0.05: 1(-1.55,1) 6(-1.55,-1) 13(1.55,-1) 18(1.55,1)
  oval 0.8x0.2 smd mask+0.05: 2(-1.45,0.6) 3(-1.45,0.2) 4(-1.45,-0.2) 5(-1.45,-0.6) 14(1.45,-0.6) 15(1.45,-0.2) 16(1.45,0.2) 17(1.45,0.6)
  oval 0.2x0.6 smd mask+0.05: 7(-1,-1.55) 12(1,-1.55) 19(1,1.55) 24(-1,1.55)
  oval 0.2x0.8 smd mask+0.05: 8(-0.6,-1.45) 9(-0.2,-1.45) 10(0.2,-1.45) 11(0.6,-1.45) 20(0.6,1.45) 21(0.2,1.45) 22(-0.2,1.45) 23(-0.6,1.45)
  rect 1.7x1.54 smd mask+0.05: 25(0,0)
  silkscreen extent -2.47,-1.7 1.7,1.7, body extent -1.55,-1.55 1.55,1.55, height 1.05
"Pin Header, 1x2" [mm] "Terminal Assembly, 1x2 Pins, Vertical, 2.54mm Pitch, Male"
  rect 1.52x1.52 hole 1.02: 1(0,0)
  round 1.52 hole 1.02: 2(2.54,0)
  silkscreen extent -1.46,-1.24 4,1.24, body extent -1.27,-1.24 3.81,1.24, height 5.89
QFN50P350X350X100_HS-21L [mm] "QFN, 20-Leads, Body 3.50x3.50mm, Pitch 0.50mm, Thermal Pad 2.05x2.05mm, IPC High Density"
  oval 0.8x0.25 smd mask+0.05: 1(-1.625,1) 2(-1.625,0.5) 3(-1.625,0) 4(-1.625,-0.5) 5(-1.625,-1) 11(1.625,-1) 12(1.625,-0.5) 13(1.625,0) 14(1.625,0.5) 15(1.625,1)
  oval 0.25x0.8 smd mask+0.05: 6(-1,-1.625) 7(-0.5,-1.625) 8(0,-1.625) 9(0.5,-1.625) 10(1,-1.625) 16(1,1.625) 17(0.5,1.625) 18(0,1.625) 19(-0.5,1.625) 20(-1,1.625)
  rect 2.05x2.05 smd mask+0.05: 21(0,0)
  silkscreen extent -2.67,-1.97 1.97,2.11, body extent -1.83,-1.83 1.83,1.83, height 1
QFN-48-7x7-4.1x4.1_N [mm] "QFN, 48-Leads, Body 7x7mm, Pitch 0.5mm, Thermal Pad 4.1x4.1mm, IPC Medium Density"
  oval 0.9x0.25 smd: 1(-3.45,2.75) 2(-3.45,2.25) 3(-3.45,1.75) 4(-3.45,1.25) 5(-3.45,0.75) 6(-3.45,0.25) 7(-3.45,-0.25) 8(-3.45,-0.75) 9(-3.45,-1.25) 10(-3.45,-1.75) 11(-3.45,-2.25) 12(-3.45,-2.75) 25(3.45,-2.75) 26(3.45,-2.25) 27(3.45,-1.75) 28(3.45,-1.25) 29(3.45,-0.75) 30(3.45,-0.25) 31(3.45,0.25) 32(3.45,0.75) 33(3.45,1.25) 34(3.45,1.75) 35(3.45,2.25) 36(3.45,2.75)
  oval 0.25x0.9 smd: 13(-2.75,-3.45) 14(-2.25,-3.45) 15(-1.75,-3.45) 16(-1.25,-3.45) 17(-0.75,-3.45) 18(-0.25,-3.45) 19(0.25,-3.45) 20(0.75,-3.45) 21(1.25,-3.45) 22(1.75,-3.45) 23(2.25,-3.45) 24(2.75,-3.45) 37(2.75,3.45) 38(2.25,3.45) 39(1.75,3.45) 40(1.25,3.45) 41(0.75,3.45) 42(0.25,3.45) 43(-0.25,3.45) 44(-0.75,3.45) 45(-1.25,3.45) 46(-1.75,3.45) 47(-2.25,3.45) 48(-2.75,3.45)
  rect 4.1x4.1 smd: 49(0,0)
  silkscreen extent -4.47,-3.7 3.7,3.7, body extent -3.55,-3.55 3.55,3.55, height 1
RESC0402(1005)_L [mm] "Chip Resistor, Body 1.0x0.5mm, IPC High Density"
  rect 0.45x0.55 smd: 1(-0.45,0) 2(0.45,0)
  body extent -0.52,-0.27 0.53,0.28, height 0.4
RESC0402(1005)_M [mm] "Chip Resistor, Body 1.0x0.5mm, IPC Low Density"
  rect 0.65x0.75 smd: 1(-0.55,0) 2(0.55,0)
  body extent -0.52,-0.28 0.53,0.28, height 0.4
RESC0402(1005)_N [mm] "Chip Resistor, Body 1.0x0.5mm, IPC Medium Density"
  rect 0.55x0.65 smd: 1(-0.5,0) 2(0.5,0)
  body extent -0.52,-0.27 0.53,0.28, height 0.4
RESC0603(1608)_M [mm] "Chip Resistor, Body 1.6x0.8mm, IPC Low Density"
  rect 1.1x1.1 smd: 1(-0.9,0) 2(0.9,0)
  silkscreen extent -0.05,-0.45 0.05,0.45, body extent -0.85,-0.47 0.85,0.47, height 0.6
RESC0603(1608)_N [mm] "Chip Resistor, Body 1.6x0.8mm, IPC Medium Density"
  rect 0.9x1 smd: 1(-0.8,0) 2(0.8,0)
  silkscreen extent -0.05,-0.4 0.05,0.4, body extent -0.85,-0.47 0.85,0.47, height 0.6
RESC0805(2012)_N [mm] "Chip Resistor, Body 2.0x1.3mm, IPC Medium Density"
  rect 1.05x1.4 smd: 1(-0.95,0) 2(0.95,0)
  silkscreen extent -0.05,-0.6 0.05,0.6, body extent -1.1,-0.67 1.1,0.68, height 0.7
RFM95W [mil] "Low Power Long Range Transceiver Module"
  rect 86x42 smd: 1(-314.95,275.6) 2(-314.95,196.86) 3(-314.95,118.12) 4(-314.95,39.38) 5(-314.95,-39.36) 6(-314.95,-118.1) 7(-314.95,-196.84) 8(-314.95,-275.58) 9(314.97,-275.58) 10(314.97,-196.84) 11(314.97,-118.1) 12(314.97,-39.36) 13(314.97,39.38) 14(314.97,118.12) 15(314.97,196.86) 16(314.97,275.6)
  silkscreen extent -315,-315 317,315, body extent -315,-313 315,313, height 88
RGY14-2050X2050TP [mm] "QFN, 14-Leads, Body 3.5x3.5mm, Pitch 0.5mm, Thermal Pad 2.05x2.05mm, TI Recommended"
  oval 0.28x0.85 smd paste-0.025 mask+0.05: 1(-0.75,1.725) 7(-0.75,-1.725) 8(0.75,-1.725) 14(0.75,1.725)
  oval 0.85x0.28 smd paste-0.025 mask+0.05: 2(-1.725,1) 3(-1.725,0.5) 4(-1.725,0) 5(-1.725,-0.5) 6(-1.725,-1) 9(1.725,-1) 10(1.725,-0.5) 11(1.725,0) 12(1.725,0.5) 13(1.725,1)
  rect 2.05x2.05 smd paste-1.025 mask+0.05: 15(0,0)
  silkscreen extent -1.98,-1.98 1.97,2.42, body extent -1.83,-1.83 1.82,1.82, height 0.05
SIP-5x2 [mil]
  rect 64x64 hole 34: 1(0,0)
  round 64 hole 34: 2(0,100) 3(100,0) 4(100,100) 5(200,0) 6(200,100) 7(300,0) 8(300,100) 9(400,0) 10(400,100)
  silkscreen extent -50,-50 450,150
"Small Solder Jumper" [mm] "Small Solder Jumper (shortcut with a drop of tin if needed)"
  round 0.525 smd paste+0 mask+0: 1(-0.337,0) 2(0.337,0)
  oval 0.52x0.63 smd paste+0 mask+0: 1(-0.335,0) 2(0.335,0)
  oval 0.51x0.71 smd paste+0 mask+0: 1(-0.33,0) 2(0.33,0)
  oval 0.5x0.76 smd paste+0 mask+0: 1(-0.325,0) 2(0.325,0)
  oval 0.49x0.8 smd paste+0 mask+0: 1(-0.32,0) 2(0.32,0)
  oval 0.475x0.84 smd paste+0 mask+0: 1(-0.312,0) 2(0.312,0)
  oval 0.465x0.865 smd paste+0 mask+0: 1(-0.308,0) 2(0.308,0)
  oval 0.45x0.897 smd paste+0 mask+0: 1(-0.3,0) 2(0.3,0)
  oval 0.425x0.943 smd paste+0 mask+0: 1(-0.288,0) 2(0.288,0)
  oval 0.4x0.981 smd paste+0 mask+0: 1(-0.275,0) 2(0.275,0)
  oval 0.375x1.013 smd paste+0 mask+0: 1(-0.262,0) 2(0.262,0)
  oval 0.35x1.04 smd paste+0 mask+0: 1(-0.25,0) 2(0.25,0)
  oval 0.325x1.063 smd paste+0 mask+0: 1(-0.238,0) 2(0.238,0)
  oval 0.3x1.082 smd paste+0 mask+0: 1(-0.225,0) 2(0.225,0)
  oval 0.275x1.098 smd paste+0 mask+0: 1(-0.212,0) 2(0.212,0)
  oval 0.25x1.112 smd paste+0 mask+0: 1(-0.2,0) 2(0.2,0)
  oval 0.225x1.125 smd paste+0 mask+0: 1(-0.188,0) 2(0.188,0)
  oval 0.2x1.137 smd paste+0 mask+0: 1(-0.175,0) 2(0.175,0)
  silkscreen extent -0.83,-0.82 0.83,0.83
SON50P200X60-10N [mm] "SON, 10-Leads, Body 3.00x2.00mm, Pitch 0.50mm, IPC Medium Density"
  rect 1.2x0.25 smd: 1(-0.845,1) 2(-0.845,0.5) 3(-0.845,0) 4(-0.845,-0.5) 5(-0.845,-1) 6(0.845,-1) 7(0.845,-0.5) 8(0.845,0) 9(0.845,0.5) 10(0.845,1)
  silkscreen extent -1.88,-1.7 1.1,1.7, body extent -0.95,-1.55 0.95,1.55, height 0.6
SON65P210X75_HS-7N [mm] "SON, 6-Leads, Body 2.10x2.10mm, Pitch 0.65mm, Thermal Pad 1.35x0.65mm, IPC Medium Density"
  rect 0.75x0.3 smd: 1(-1.015,0.65) 2(-1.015,0) 3(-1.015,-0.65) 4(1.015,-0.65) 5(1.015,0) 6(1.015,0.65)
  rect 0.65x1.35 smd: 7(0,0)
  silkscreen extent -1.5,-1.2 1.05,1.25, body extent -1.05,-1.05 1.05,1.05, height 0.75
SON100P300X110_HS-7N [mm] "SON, 6-Leads, Body 3.00x3.00mm, Pitch 1.00mm, Thermal Pad 2.40x1.50mm, IPC Medium Density"
  rect 0.8x0.4 smd: 1(-1.46,1) 2(-1.46,0) 3(-1.46,-1) 4(1.46,-1) 5(1.46,0) 6(1.46,1)
  rect 1.5x2.4 smd: 7(0,0)
  silkscreen extent -2.1,-1.65 1.65,1.7, body extent -1.5,-1.5 1.5,1.5, height 1.1
SW_DTSM-62N [mil] "ADTSM62"
  rrect50% 57x45 smd: 1(157.87,-88.58) 2(-157.48,-88.58) 3(157.87,88.19) 4(-157.48,88.19)
  silkscreen extent -115,-124 115,124, body extent -177,-122 177,122, height 177
TSW-150-07-G-S [mm] "Terminal Assembly, 1 Pin, Vertical, 2.54mm Pitch, Male"
  rect 1.5x1.5 hole 1: 1(0,0)
  silkscreen extent -1.27,-1.27 1.27,1.27, body extent -1.25,-1.25 1.25,1.25, height 9.5
YZF0008AHAH [mm] "BGA, 8-Leads, Body 1.53x1.53mm, Pitch 0.50mm"
  round 0.25 smd: A1(-0.5,0.5) A2(0,0.5) A3(0.5,0.5) B1(-0.5,0) B3(0.5,0) C1(-0.5,-0.5) C2(0,-0.5) C3(0.5,-0.5)
  silkscreen extent -1.02,-0.82 0.83,1.03, body extent -0.76,-0.76 0.76,0.77, height 0.63
Z5+1_N [mm] "SOT23, 5-Leads, Body 2.9x1.6mm, Pitch 0.95mm, Lead Span 2.8mm, IPC Medium Density"
  rect 1.1x0.65 smd: 1(-1.2,0.95) 2(-1.2,0) 3(-1.2,-0.95) 4(1.2,-0.95) 5(1.2,0.95)
  silkscreen extent -1.32,-1.5 0.25,1.95, body extent -0.82,-1.5 0.82,1.5, height 1.1

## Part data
A1: library part CMP-00038-1
C1 C4 C39: library part CMP-1034-02136-1, "CAP 4.7uF 6.3V ±10% 0402 (1005 Metric) Thickness 0.6mm SMD", Case-EIA=0402, Case-Metric=1005, Rated Voltage="6.3 V", Tolerance=±10%
C2 C40: library part CMP-1034-02072-1, "CAP 100nF 25V ±10% 0402 (1005 Metric) Thickness 0.6mm SMD", Case-EIA=0402, Case-Metric=1005, Rated Voltage="25 V", Tolerance=±10%
C3: library part CMP-1034-01880-1, "CAP 10nF 25V ±10% 0402 (1005 Metric) Thickness 0.6mm SMD", Case-EIA=0402, Case-Metric=1005, Rated Voltage="25 V", Tolerance=±10%
C5 C41: library part CMP-1036-04939-1, "CAP 22uF 6.3V ±20% 0805 (2012 Metric) Thickness 1.45mm SMD", Case-EIA=0805, Case-Metric=2012, Rated Voltage="6.3 V", Tolerance=±20%
C6 C7 C8 C16 C18 C19 C22 C25 C26 C27 C28 C29 C35 C36 C38: library part CMP-1036-04401-1, "CAP 100nF 16V ±10% 0805 (2012 Metric) Thickness 1.45mm SMD", Case-EIA=0805, Case-Metric=2012, Rated Voltage="16 V", Tolerance=±10%
C9 C10: library part CMP-1034-00808-1, "CAP 15pF 25V ±5% 0402 (1005 Metric) Thickness 0.6mm SMD", Case-EIA=0402, Case-Metric=1005, Rated Voltage="25 V", Tolerance=±5%
C11 C12: library part CMP-1036-01312-1, "CAP 27pF 10V ±10% 0805 (2012 Metric) Thickness 1mm SMD", Case-EIA=0805, Case-Metric=2012, Rated Voltage="10 V", Tolerance=±10%
C13: library part CMP-1036-04536-1, "CAP 220nF 16V ±20% 0805 (2012 Metric) Thickness 1.45mm SMD", Case-EIA=0805, Case-Metric=2012, Rated Voltage="16 V", Tolerance=±20%
C14 C17: library part CMP-1036-04748-1, "CAP 1uF 16V ±20% 0805 (2012 Metric) Thickness 1.45mm SMD", Case-EIA=0805, Case-Metric=2012, Rated Voltage="16 V", Tolerance=±20%
C15: library part CMP-1036-03818-1, "CAP 10nF 16V ±5% 0805 (2012 Metric) Thickness 1mm SMD", Case-EIA=0805, Case-Metric=2012, Rated Voltage="16 V", Tolerance=±5%
C30: library part CMP-1036-01943-1, "CAP 100pF 16V ±10% 0805 (2012 Metric) Thickness 1mm SMD", Case-EIA=0805, Case-Metric=2012, Rated Voltage="16 V", Tolerance=±10%
C31 C33: library part CMP-1036-03565-1, "CAP 4.7nF 16V ±10% 0805 (2012 Metric) Thickness 1.45mm SMD", Case-EIA=0805, Case-Metric=2012, Rated Voltage="16 V", Tolerance=±10%
C32: library part CMP-1036-00386-1, "CAP 3.3pF 10V ±0.1pF 0805 (2012 Metric) Thickness 0.75mm SMD", Case-EIA=0805, Case-Metric=2012, Rated Voltage="10 V", Tolerance=±0.1pF
C34: library part CMP-1036-00938-1, "CAP 12pF 25V ±5% 0805 (2012 Metric) Thickness 1mm SMD", Case-EIA=0805, Case-Metric=2012, Rated Voltage="25 V", Tolerance=±5%
D1 D2: library part CMP-1426-00012-1, "SMD mono-color Chip LED, WL-SMCW, Yellow", Color=Yellow, Manufacturer="Wuerth Elektronik"
D3: library part CMP-1154-00014-1, "Single Silicon Schottky Diode, 130 mA IF Max, SOT23, Green", Manufacturer=Infineon
D4: library part CMP-00132-1, "RF Schottky Diode, Zero Bias, Dual Series, 2 V, 1 mA, 250 mV, 0.3 pF, SOT-323 , RoHS Complian", Capacitance @ Vr, F="0.3pF @ 1V, 1MHz", Current - Max=-, Manufacturer="Broadcom Limited", Package / Case="SC-70, SOT-323", Supplier Device Package=SOT-323, Supplier Part Number=516-2558-ND, Voltage - Peak Reverse (Max)=2V
H_IN X7 X8 X19: library part CMP-00100-1, "2 CONTACT(S), MALE, STRAIGHT TWO PART BOARD CONNECTOR, SOLDER, 2.54mm, 1x2", Color=Black, Manufacturer="Amphenol FCI", Manufacturer Part Number=68000-102HLF, Supplier Part Number=609-3500-ND
J1 J2 J4: library part CMP-00005-1
J6 J7: library part CMP-00118-1, "CONN SMA JACK 50 OHM EDGE MNT", Dielectric Material="Polytetrafluoroethylene (PTFE)", Frequency - Max=18GHz, Housing Color=Gold, Manufacturer="Amphenol-RF Division", Operating Temperature="-65°C ~ 165°C", Supplier Part Number=ACX1652-ND, Voltage Rating=-
L1: library part CMP-00081-1, "Fixed Inductors LPS4018 Low Profile 22uH 0.9A 20% SMD", Inductance="22 uH", Manufacturer=Coilcraft, Maximum DC Current="830 mA", Maximum DC Resistance="360 mOhms", Operating Temperature Range="- 40 C to + 85 C", Self Resonant Frequency="26 MHz", Supplier Part Number=994-LPS4018-223MRC, Test Frequency="100 kHz", Tolerance="20 %"
L2: library part CMP-00083-1, "Fixed Inductors LPS4018 Low Profile 10uH 1.25A 20% SMD", Inductance="10 uH", Manufacturer=Coilcraft, Maximum DC Current="1.3 A", Maximum DC Resistance="200 mOhms", Operating Temperature Range="- 40 C to + 85 C", Self Resonant Frequency="40 MHz", Supplier Part Number=994-LPS4018-103MRB, Test Frequency="100 kHz", Tolerance="20 %"
L3: library part CMP-00133-1, "FIXED IND 30NH 420MA 230 MOHM 0603", Current - Saturation=-, Current Rating=420mA, DC Resistance (DCR)="230 mOhm Max", Frequency - Self Resonant=3.3GHz, Frequency - Test=100MHz, Inductance=30nH, Manufacturer="Murata Electronics North America", Operating Temperature="-55°C ~ 125°C", Package / Case="0603 (1608 Metric)", Q @ Freq="40 @ 250MHz", Supplier Part Number=490-6883-1-ND, Tolerance=±5%
L5: library part CMP-00241-1, "10µH Shielded Wirewound Inductor 1A 460 mOhm Max 1008 (2520 Metric)", Current - Saturation=-, Current Rating=1A, DC Resistance (DCR)="460 mOhm Max", Frequency - Test=1MHz, Inductance=10µH, Manufacturer="Murata Electronics North America", Manufacturer Part Number=1239AS-H-100M{}P2, Operating Temperature="-40°C ~ 85°C", Package / Case="1008 (2520 Metric)", Supplier Part Number=490-10563-1-ND, Tolerance=±20%
M1 M2 M3 M4: library part CMP-00023-1, "Mounting Hole, 7.2mm pad, 3.2mm plated hole"
Q1: "N-Channel Power MOSFET", Drain Current (Cont.)=3A, Drain Current (Pulsed)=20A, DrainSource Voltage=20V, Operating Range="-55C to +150C"
R1 R31: library part CMP-1011-00950-1, "7M87 0.063W 1% 0402 (1005 Metric)  SMD", Case-EIA=0402, Case-Metric=1005, Power="0.063 W", Tolerance="1 %"
R2: library part CMP-1011-00947-1, "7M32 0.063W 1% 0402 (1005 Metric)  SMD", Case-EIA=0402, Case-Metric=1005, Power="0.063 W", Tolerance="1 %"
R3: library part CMP-1011-00832-1, "698K 0.063W 1% 0402 (1005 Metric)  SMD", Case-EIA=0402, Case-Metric=1005, Power="0.063 W", Tolerance="1 %"
R4: library part CMP-1011-00944-1, "6M81 0.063W 1% 0402 (1005 Metric)  SMD", Case-EIA=0402, Case-Metric=1005, Power="0.063 W", Tolerance="1 %"
R5 R7: library part CMP-1011-00933-1, "5M49 0.063W 1% 0402 (1005 Metric)  SMD", Case-EIA=0402, Case-Metric=1005, Power="0.063 W", Tolerance="1 %"
R6 R32: library part CMP-1011-00931-1, "5M23 0.063W 1% 0402 (1005 Metric)  SMD", Case-EIA=0402, Case-Metric=1005, Power="0.063 W", Tolerance="1 %"
R8 R9: library part CMP-1012-00066-1, "470R 0.1W 5% 0603 (1608 Metric)  SMD", Case-EIA=0603, Case-Metric=1608, Power="0.1 W", Tolerance="5 %"
R10 R14 R15: library part CMP-1013-00510-1, "1K 0.125W 1% 0805 (2012 Metric)  SMD", Case-EIA=0805, Case-Metric=2012, Power="0.125 W", Tolerance="1 %"
R11 R16 R17 R18 R22: library part CMP-1013-00623-1, "10K 0.125W 1% 0805 (2012 Metric)  SMD", Case-EIA=0805, Case-Metric=2012, Power="0.125 W", Tolerance="1 %"
R12 R13: library part CMP-1013-00567-1, "3K3 0.125W 1% 0805 (2012 Metric)  SMD", Case-EIA=0805, Case-Metric=2012, Power="0.125 W", Tolerance="1 %"
R19: library part CMP-1013-00815-1, "499K 0.125W 1% 0805 (2012 Metric)  SMD", Case-EIA=0805, Case-Metric=2012, Power="0.125 W", Tolerance="1 %"
R20 R21: library part CMP-1012-00850-1, "1M02 0.1W 1% 0603 (1608 Metric)  SMD", Case-EIA=0603, Case-Metric=1608, Power="0.1 W", Tolerance="1 %"
R23: library part CMP-1013-00728-1, "84K5 0.125W 1% 0805 (2012 Metric)  SMD", Case-EIA=0805, Case-Metric=2012, Power="0.125 W", Tolerance="1 %"
R24: library part CMP-1013-00867-1, "1M5 0.125W 1% 0805 (2012 Metric)  SMD", Case-EIA=0805, Case-Metric=2012, Power="0.125 W", Tolerance="1 %"
R25: library part CMP-1013-00849-1, "1M 0.125W 1% 0805 (2012 Metric)  SMD", Case-EIA=0805, Case-Metric=2012, Power="0.125 W", Tolerance="1 %"
R26: library part CMP-1013-00901-1, "3M 0.125W 1% 0805 (2012 Metric)  SMD", Case-EIA=0805, Case-Metric=2012, Power="0.125 W", Tolerance="1 %"
R30: library part CMP-1011-00949-1, "7M68 0.063W 1% 0402 (1005 Metric)  SMD", Case-EIA=0402, Case-Metric=1005, Power="0.063 W", Tolerance="1 %"
R33: library part CMP-1011-00929-1, "5M1 0.063W 1% 0402 (1005 Metric)  SMD", Case-EIA=0402, Case-Metric=1005, Power="0.063 W", Tolerance="1 %"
